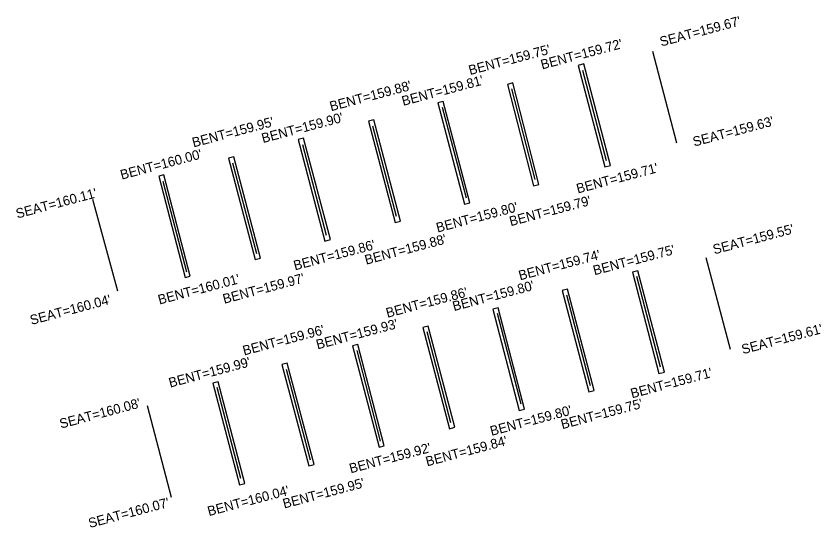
# Model space of a CAD drawing. Extents: x 2107167 to 2121551, y 865392 to 868477.
# Drawn here: x 2110124.8 to 2110458.4, y 867100.9 to 867313.1 of the extents above; entities that cross this region are included whole.
import ezdxf

# ---------------------------------------------------------------- set-up
doc = ezdxf.new("R2010")
doc.units = 0
for name, color, linetype in [('RD_EX_Bridge', 7, 'Continuous'), ('RD_EX_Bridge_txCode', 7, 'Continuous'), ('RD_EX_Conc', 7, 'Continuous')]:
    doc.layers.add(name, color=color, linetype=linetype)

msp = doc.modelspace()

# ---------------------------------------------------------------- linework, layer by layer
at = {"layer": 'RD_EX_Bridge'}
for p, q in [((2110388.66, 867298.58), (2110398.52, 867260.49)), ((2110359.62, 867290.69), (2110369.39, 867253.29)), ((2110330.13, 867282.9), (2110339.84, 867245.31)), ((2110301.47, 867275.31), (2110311.31, 867237.72)), ((2110272.47, 867267.58), (2110282.39, 867230.08)), ((2110243.53, 867259.92), (2110253.36, 867222.34)), ((2110214.53, 867252.25), (2110224.37, 867214.61)), ((2110185.59, 867244.68), (2110195.48, 867207.08)), ((2110156.5, 867237.17), (2110166.87, 867199.24)), ((2110410.69, 867213.03), (2110420.78, 867175.05)), ((2110381.96, 867205.22), (2110391.8, 867167.63)), ((2110352.98, 867197.54), (2110362.71, 867159.91)), ((2110324.19, 867189.97), (2110333.99, 867152.3)), ((2110295.02, 867182.39), (2110304.89, 867144.56)), ((2110266.01, 867174.44), (2110275.77, 867136.88)), ((2110236.71, 867166.73), (2110246.69, 867129.09)), ((2110207.93, 867159.19), (2110217.79, 867121.47)), ((2110179.05, 867151.72), (2110189.12, 867113.6))]:
    msp.add_line(p, q, dxfattribs=at)
at = {"layer": 'RD_EX_Conc'}
for points in [[(2110357.86, 867292.64), (2110368.8, 867250.56), (2110371.15, 867251.17), (2110360.21, 867293.25)], [(2110328.48, 867284.79), (2110339.33, 867242.77), (2110341.53, 867243.34), (2110330.68, 867285.36)], [(2110299.59, 867277.17), (2110310.69, 867235.16), (2110312.87, 867235.74), (2110301.76, 867277.74)], [(2110270.87, 867269.53), (2110281.97, 867227.54), (2110284.17, 867228.12), (2110273.07, 867270.11)], [(2110241.74, 867261.89), (2110252.83, 867219.82), (2110255.05, 867220.41), (2110243.96, 867262.48)], [(2110212.85, 867254.23), (2110223.87, 867212.14), (2110226.08, 867212.72), (2110215.05, 867254.81)], [(2110183.91, 867246.7), (2110194.8, 867204.68), (2110196.87, 867205.22), (2110185.98, 867247.24)], [(2110380.28, 867206.91), (2110391.27, 867164.91), (2110393.53, 867165.5), (2110382.54, 867207.5)], [(2110351.18, 867199.3), (2110362.16, 867157.27), (2110364.4, 867157.85), (2110353.42, 867199.88)], [(2110322.4, 867191.61), (2110333.35, 867149.62), (2110335.56, 867150.2), (2110324.62, 867192.19)], [(2110293.38, 867183.98), (2110304.48, 867142.03), (2110306.69, 867142.61), (2110295.58, 867184.56)], [(2110264.26, 867176.34), (2110275.24, 867134.36), (2110277.43, 867134.93), (2110266.45, 867176.91)], [(2110234.95, 867168.61), (2110246.17, 867126.62), (2110248.38, 867127.21), (2110237.16, 867169.2)], [(2110206.28, 867160.85), (2110217.38, 867118.72), (2110219.59, 867119.31), (2110208.48, 867161.43)]]:
    msp.add_lwpolyline(points, close=True, dxfattribs=at)

# ---------------------------------------------------------------- texts
at = {"layer": 'RD_EX_Bridge_txCode'}
for s, p in [("SEAT=159.67'", (2110392.22, 867300.45)), ("BENT=159.75'", (2110312.97, 867288.63)), ("BENT=159.72'", (2110342.85, 867290.95)), ("BENT=159.81'", (2110285.25, 867275.85)), ("BENT=159.88'", (2110255.36, 867273.64)), ("BENT=159.95'", (2110198.34, 867258.64)), ("BENT=159.90'", (2110227.12, 867260.43)), ("SEAT=159.63'", (2110405.91, 867258.97)), ("BENT=160.00'", (2110168.54, 867245.26)), ("BENT=159.71'", (2110357.65, 867239.52)), ("SEAT=160.11'", (2110125.26, 867229.16)), ("BENT=159.79'", (2110329.84, 867225.97)), ("BENT=159.80'", (2110299.51, 867223.33)), ("SEAT=159.55'", (2110414.23, 867214.29)), ("BENT=159.88'", (2110269.88, 867210)), ("BENT=159.86'", (2110240.38, 867207.65)), ("BENT=159.75'", (2110364.57, 867205.61)), ("BENT=159.74'", (2110333.7, 867203.51)), ("BENT=160.01'", (2110184.19, 867193.48)), ("BENT=159.97'", (2110211.05, 867193.8)), ("BENT=159.80'", (2110306.3, 867190.77)), ("SEAT=160.04'", (2110131.11, 867185.04)), ("BENT=159.86'", (2110278.69, 867188)), ("BENT=159.96'", (2110219.3, 867172.37)), ("BENT=159.93'", (2110249.75, 867174.9)), ("SEAT=159.61'", (2110426.13, 867172.89)), ("BENT=159.99'", (2110188.63, 867159.06)), ("BENT=159.71'", (2110380.11, 867154.61)), ("SEAT=160.08'", (2110143.37, 867142.06)), ("BENT=159.75'", (2110351.22, 867141.81)), ("BENT=159.80'", (2110321.88, 867139.04)), ("BENT=159.84'", (2110295.16, 867126.4)), ("BENT=159.92'", (2110263.49, 867123.52)), ("BENT=159.95'", (2110235.92, 867108.92)), ("BENT=160.04'", (2110204.71, 867105.78)), ("SEAT=160.07'", (2110155.31, 867100.85))]:
    msp.add_text(s, height=4, rotation=14.858, dxfattribs=at).set_placement(p)

doc.saveas('drawing.dxf')
